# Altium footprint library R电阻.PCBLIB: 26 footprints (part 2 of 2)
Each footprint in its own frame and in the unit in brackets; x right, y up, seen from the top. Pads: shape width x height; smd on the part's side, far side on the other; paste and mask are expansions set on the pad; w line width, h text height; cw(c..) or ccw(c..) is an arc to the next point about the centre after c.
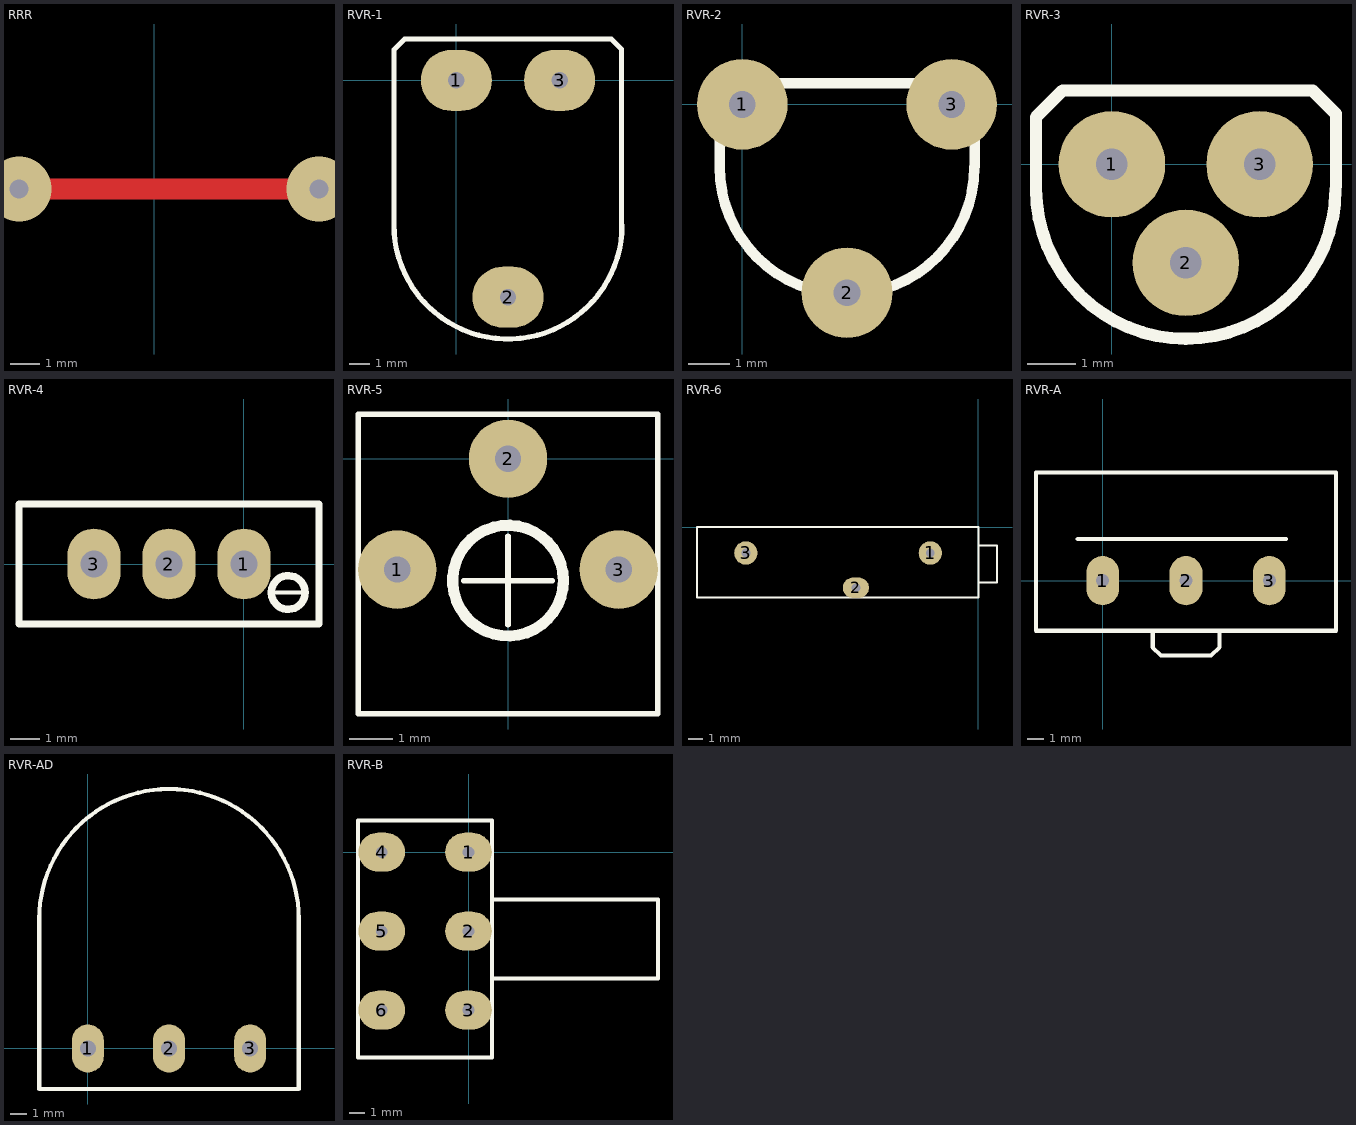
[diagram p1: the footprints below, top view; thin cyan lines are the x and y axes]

## RRR [mm]
via 5.588,0 diameter 2.2 hole 0.65
via -4.572,0 diameter 2.2 hole 0.65
TopLayer:
  lines w0.7: -4.572,0 5.588,0

## RVR-1 [mm]
pads (3):
  oval 3.5x3 hole 0.8: 1(0,0) 2(2.54,-10.668) 3(5.08,0)
TopOverlay:
  lines w0.254: 8.128,-7.62 8.128,1.524 7.62,2.032 -2.54,2.032 -3.071,1.501 -3.071,-7.112 ccw(c2.54,-7.112) 8.151,-7.112

## RVR-2 [mm]
pads (3):
  round 2.2 hole 0.65: 1(0,0) 2(2.54,-4.572) 3(5.08,0)
TopOverlay:
  lines w0.254: 5.588,0 5.08,0.508 0,0.508 -0.55,-0.042 -0.55,-1.524 ccw(c2.54,-1.524) 5.63,-1.524 ; 5.639,-1.499 5.639,-0.017

## RVR-3 [mm]
pads (3):
  round 2.2 hole 0.65: 1(0,0) 2(1.524,-2.032) 3(3.048,0)
TopOverlay:
  lines w0.254: 4.614,-0.508 cw(c1.524,-0.508) -1.566,-0.508 -1.566,0.974 -1.016,1.524 4.14,1.524 4.623,1.041 ; 4.623,-0.457 4.623,1.025

## RVR-4 [mm]
pads (3):
  oval 1.8x2.4 hole 0.9: 1(0,0) 2(-2.54,0) 3(-5.08,0)
TopOverlay:
  circle w0.254: c1.499,-0.965 r0.571
  lines w0.127: 0.94,-0.965 2.069,-0.965
  lines w0.24: -7.62,-2.032 2.54,-2.032 2.54,2.032 -7.62,2.032 -7.62,-2.032

## RVR-5 [mm]
pads (3):
  round 1.8 hole 0.6: 1(-2.54,-2.54) 2(0,0) 3(2.54,-2.54)
TopOverlay:
  circle w0.254: c0,-2.794 r1.27
  lines w0.127: -1.016,-2.794 1.016,-2.794 ; 0,-3.81 0,-1.778 ; -3.429,-5.842 -3.429,1.016 0.127,1.016 3.429,1.016 3.429,-5.842 -3.429,-5.842

## RVR-6 [mm]
pads (3):
  round 1.6 hole 0.6: 1(-3.302,-1.778) 3(-15.951,-1.778)
  oval 1.8x1.4 hole 0.6: 2(-8.407,-4.166)
TopOverlay:
  lines w0.127: 0,-3.81 1.27,-3.81 1.27,-1.27 0,-1.27 ; -19.304,-4.826 -19.304,0 0,0 0,-4.826 -19.304,-4.826

## RVR-A [mm]
pads (3):
  oval 2x3 hole 0.8: 1(0,0) 2(5.08,0) 3(10.16,0)
TopOverlay:
  lines w0.254: -1.524,2.54 11.176,2.54 ; 3.048,-3.048 3.048,-4.064 3.556,-4.572 6.604,-4.572 7.112,-4.064 7.112,-3.048 ; -4.064,-3.048 -4.064,6.604 14.224,6.604 14.224,0 14.224,-3.048 -4.064,-3.048

## RVR-AD [mm]
pads (3):
  oval 2x3 hole 1: 1(0,0) 2(5.08,0) 3(10.16,0)
TopOverlay:
  lines w0.254: -3.048,-2.54 13.208,-2.54 13.208,8.128 ccw(c5.08,8.128) -3.048,8.128 -3.048,-2.54

## RVR-B [mm]
pads (6):
  oval 3x2.5 hole 0.75: 1(0,0) 2(0,-5.08) 3(0,-10.16) 4(-5.588,0) 5(-5.588,-5.08) 6(-5.588,-10.16)
TopOverlay:
  lines w0.254: 1.524,-8.128 12.192,-8.128 12.192,-3.048 1.524,-3.048 ; -7.112,-13.208 1.524,-13.208 1.524,2.032 -7.112,2.032 -7.112,-13.208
